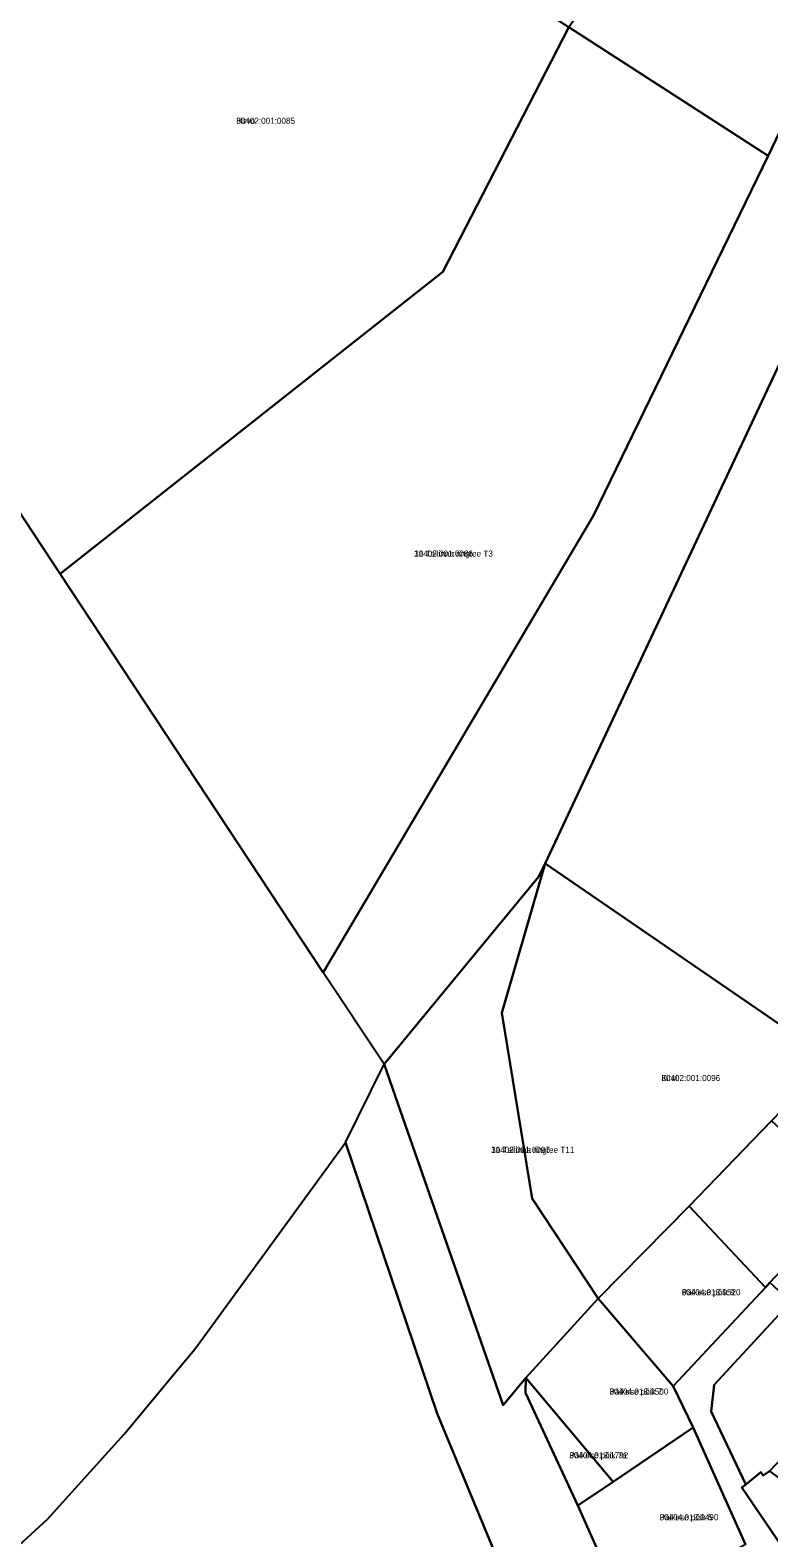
# Model space of a CAD drawing. Extents: x 542681 to 554572, y 6566489 to 6580482.
# Drawn here: x 543424.5 to 543606.8, y 6575908.9 to 6576281 of the extents above; entities that cross this region are included whole.
import ezdxf

# ---------------------------------------------------------------- set-up
doc = ezdxf.new("R2010")
doc.units = 0
for name, color, linetype in [('L_AADRESS', 7, 'Continuous'), ('PIIR', 7, 'Continuous'), ('TUNNUS', 7, 'Continuous')]:
    doc.layers.add(name, color=color, linetype=linetype)

msp = doc.modelspace()

# ---------------------------------------------------------------- linework, layer by layer
at = {"layer": 'PIIR'}
for points in [[(543740.67, 6576463.36), (543624.99, 6576231.86), (543610.08, 6576200.08), (543551.63, 6576075.36), (543550.03, 6576072.1), (543511.86, 6576025.82), (543496.84, 6576048.42), (543563.51, 6576161.2), (543606.64, 6576249.99), (543633.91, 6576307.07)], [(543559.92, 6575855.18), (543524.96, 6575939.63), (543502.31, 6576006.5), (543511.86, 6576025.82), (543515.26, 6576016.09), (543541.19, 6575941.63), (543546.82, 6575948.41), (543546.76, 6575944.72), (543559.69, 6575916.88), (543571.38, 6575890.38)], [(543601.06, 6575907.27), (543588.12, 6575936.11), (543583.17, 6575946.33), (543605.92, 6575970.66), (543607.06, 6575971.92), (543612.18, 6575967.19), (543593.32, 6575946.67), (543592.53, 6575940.1), (543601.14, 6575922.1), (543600.14, 6575921.33), (543624.52, 6575885.37)]]:
    msp.add_lwpolyline(points, dxfattribs=at)
for points in [[(543442.21, 6576356.03), (543557.43, 6576281.74), (543526.37, 6576221.38), (543431.91, 6576146.83), (543393.3, 6576205.35)], [(543591.9, 6576332.78), (543633.91, 6576307.07), (543606.64, 6576249.99), (543557.43, 6576281.74)], [(543431.91, 6576146.83), (543526.37, 6576221.38), (543557.43, 6576281.74), (543606.64, 6576249.99), (543563.51, 6576161.2), (543496.84, 6576048.42)], [(543610.08, 6576200.08), (543678.38, 6576251.99), (543771.59, 6576182.76), (543746.47, 6576156.82), (543720.94, 6576129.63), (543717.45, 6576126.42), (543695.26, 6576105.01), (543680.88, 6576090.14), (543666.51, 6576074.33), (543651.27, 6576057.86), (543637.1, 6576042.64), (543622.09, 6576026.97), (543551.63, 6576075.36)], [(543551.63, 6576075.36), (543540.87, 6576038.52), (543548.38, 6575992.67), (543564.69, 6575967.94), (543546.82, 6575948.41), (543541.19, 6575941.63), (543515.26, 6576016.09), (543511.86, 6576025.82), (543550.03, 6576072.1)], [(543551.63, 6576075.36), (543622.09, 6576026.97), (543607.41, 6576011.85), (543587.11, 6575990.79), (543564.69, 6575967.94), (543548.38, 6575992.67), (543540.87, 6576038.52)], [(543624.15, 6575990.1), (543607.06, 6575971.92), (543605.92, 6575970.66), (543587.11, 6575990.79), (543607.41, 6576011.85), (543635.14, 6575986.48), (543631.3, 6575982.69)], [(543465.13, 6575955.5), (543502.31, 6576006.5), (543524.96, 6575939.63), (543559.92, 6575855.18), (543535.31, 6575864.03), (543457.6, 6575843.27), (543417.11, 6575860.63), (543399.83, 6575862.85), (543338.02, 6575804.77), (543150.41, 6575612.78), (543209.06, 6575687.37), (543263.95, 6575744.6), (543407.75, 6575894.29), (543428.81, 6575913.5), (543447.69, 6575934.5), (543460.89, 6575950.39)], [(543605.92, 6575970.66), (543583.17, 6575946.33), (543564.69, 6575967.94), (543587.11, 6575990.79)], [(543583.17, 6575946.33), (543588.12, 6575936.11), (543568.38, 6575922.77), (543546.82, 6575948.41), (543564.69, 6575967.94)], [(543629.4, 6575949.06), (543606.93, 6575925.4), (543605.37, 6575924.26), (543604.84, 6575925.1), (543601.14, 6575922.1), (543592.53, 6575940.1), (543593.32, 6575946.67), (543612.18, 6575967.19)], [(543568.38, 6575922.77), (543559.69, 6575916.88), (543546.76, 6575944.72), (543546.82, 6575948.41)], [(543559.69, 6575916.88), (543568.38, 6575922.77), (543588.12, 6575936.11), (543601.06, 6575907.27), (543571.38, 6575890.38)], [(543601.14, 6575922.1), (543604.84, 6575925.1), (543605.37, 6575924.26), (543606.93, 6575925.4), (543624.03, 6575912.94), (543640.79, 6575903.01), (543624.52, 6575885.37), (543600.14, 6575921.33)]]:
    msp.add_lwpolyline(points, close=True, dxfattribs=at)

# ---------------------------------------------------------------- texts
at = {"layer": 'L_AADRESS'}
for s, p in [('Hirvo', (543475.36, 6576257.89)), ('11 Tallinna ringtee T3', (543519.27, 6576151.08)), ('Kirsi', (543580.28, 6576021.65)), ('11 Tallinna ringtee T11', (543538.27, 6576003.92)), ('Päikese põik 9', (543585.3, 6575968.78)), ('Päikese põik 7', (543567.47, 6575944.27)), ('Päikese põik 7a', (543557.57, 6575928.54)), ('Päikese põik 5', (543579.84, 6575913.24))]:
    msp.add_text(s, height=1.5, dxfattribs=at).set_placement(p)
at = {"layer": 'TUNNUS'}
for s, p in [('30402:001:0085', (543475.36, 6576257.89)), ('30402:001:0086', (543519.27, 6576151.08)), ('30402:001:0096', (543580.28, 6576021.65)), ('30402:001:0097', (543538.27, 6576003.92)), ('30404:013:0520', (543585.3, 6575968.78)), ('30404:013:0500', (543567.47, 6575944.27)), ('30404:013:1792', (543557.57, 6575928.54)), ('30404:013:0490', (543579.84, 6575913.24))]:
    msp.add_text(s, height=1.5, dxfattribs=at).set_placement(p)

doc.saveas('drawing.dxf')
